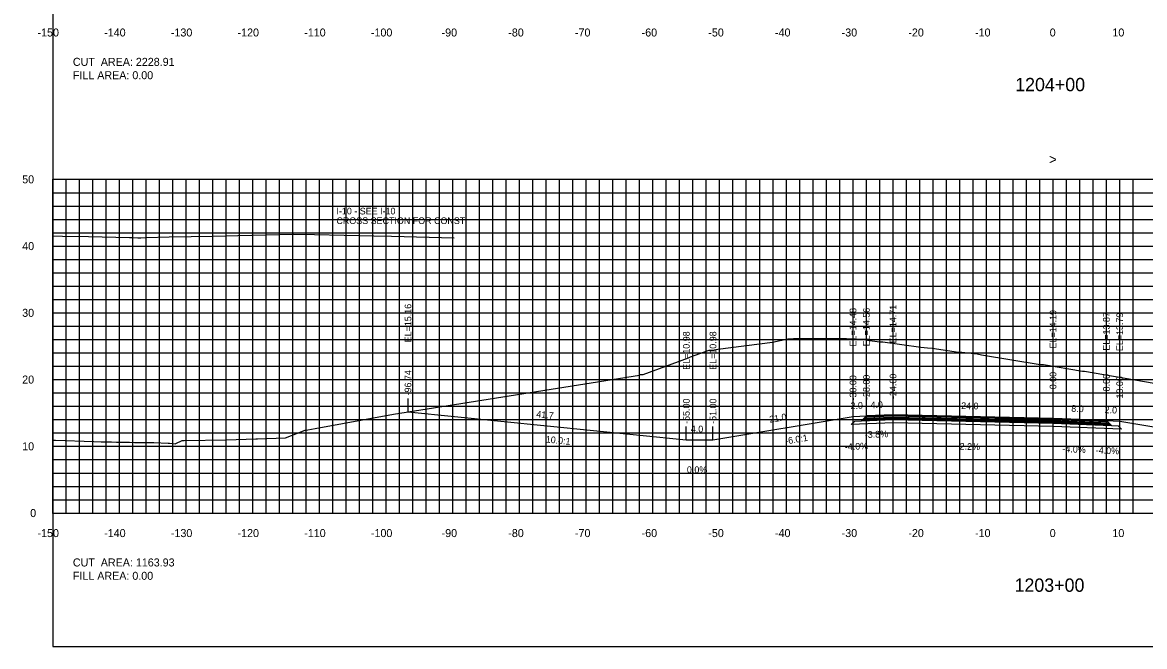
# Model space of a CAD drawing. Extents: x 1797305 to 1804485, y 245831 to 250849.
# Drawn here: x 1802476.4 to 1802644.7, y 250079.4 to 250172.9 of the extents above; entities that cross this region are included whole.
import ezdxf

# ---------------------------------------------------------------- set-up
doc = ezdxf.new("R2010")
doc.units = 0
for name, color, linetype in [('1', 7, 'Continuous'), ('10', 7, 'Continuous'), ('29', 7, 'Continuous'), ('60', 7, 'Continuous'), ('ALIGN-CARP', 7, 'Continuous'), ('BASE', 7, 'Continuous'), ('CL-CNST', 7, 'Continuous'), ('EDPV-LINE', 7, 'Continuous'), ('Level 31', 7, 'Continuous'), ('Level 62', 7, 'Continuous'), ('LIMT-CSLINE', 7, 'Continuous'), ('M-ROADS', 7, 'Continuous'), ('SURVEY - DRAINAGE - Area Shapes', 7, 'Continuous'), ('SURVEY - DRAINAGE - Bridge Hydraulic Data - Points - Locators', 7, 'Continuous')]:
    doc.layers.add(name, color=color, linetype=linetype)

msp = doc.modelspace()

# ---------------------------------------------------------------- linework, layer by layer
for p, q in [((1802534.26, 250114.59), (1802534.26, 250116.59)), ((1802601, 250113.92), (1802601, 250115.92)), ((1802603, 250114), (1802603, 250116)), ((1802607, 250114.15), (1802607, 250116.15)), ((1802631, 250113.62), (1802631, 250115.62)), ((1802639, 250113.3), (1802639, 250115.3)), ((1802641, 250113.22), (1802641, 250115.22)), ((1802576, 250110.42), (1802576, 250112.42)), ((1802580, 250110.42), (1802580, 250112.42))]:
    msp.add_line(p, q)
msp.add_lwpolyline([(1802481, 250079.43), (1802781, 250079.43), (1802781, 250269.43), (1802481, 250269.43)], close=True)
at = {"layer": '29'}
for p, q in [((1802481, 250149.43), (1802781, 250149.43)), ((1802481, 250099.43), (1802481, 250149.43)), ((1802483, 250099.43), (1802483, 250149.43)), ((1802485, 250099.43), (1802485, 250149.43)), ((1802487, 250099.43), (1802487, 250149.43)), ((1802489, 250099.43), (1802489, 250149.43)), ((1802491, 250099.43), (1802491, 250149.43)), ((1802493, 250099.43), (1802493, 250149.43)), ((1802495, 250099.43), (1802495, 250149.43)), ((1802497, 250099.43), (1802497, 250149.43)), ((1802499, 250099.43), (1802499, 250149.43)), ((1802501, 250099.43), (1802501, 250149.43)), ((1802503, 250099.43), (1802503, 250149.43)), ((1802505, 250099.43), (1802505, 250149.43)), ((1802507, 250099.43), (1802507, 250149.43)), ((1802509, 250099.43), (1802509, 250149.43)), ((1802511, 250099.43), (1802511, 250149.43)), ((1802513, 250099.43), (1802513, 250149.43)), ((1802515, 250099.43), (1802515, 250149.43)), ((1802517, 250099.43), (1802517, 250149.43)), ((1802519, 250099.43), (1802519, 250149.43)), ((1802521, 250099.43), (1802521, 250149.43)), ((1802523, 250099.43), (1802523, 250149.43)), ((1802525, 250099.43), (1802525, 250149.43)), ((1802527, 250099.43), (1802527, 250149.43)), ((1802529, 250099.43), (1802529, 250149.43)), ((1802531, 250099.43), (1802531, 250149.43)), ((1802533, 250099.43), (1802533, 250149.43)), ((1802535, 250099.43), (1802535, 250149.43)), ((1802537, 250099.43), (1802537, 250149.43)), ((1802539, 250099.43), (1802539, 250149.43)), ((1802541, 250099.43), (1802541, 250149.43)), ((1802543, 250099.43), (1802543, 250149.43)), ((1802545, 250099.43), (1802545, 250149.43)), ((1802547, 250099.43), (1802547, 250149.43)), ((1802549, 250099.43), (1802549, 250149.43)), ((1802551, 250099.43), (1802551, 250149.43)), ((1802553, 250099.43), (1802553, 250149.43)), ((1802555, 250099.43), (1802555, 250149.43)), ((1802557, 250099.43), (1802557, 250149.43)), ((1802559, 250099.43), (1802559, 250149.43)), ((1802561, 250099.43), (1802561, 250149.43)), ((1802563, 250099.43), (1802563, 250149.43)), ((1802565, 250099.43), (1802565, 250149.43)), ((1802567, 250099.43), (1802567, 250149.43)), ((1802569, 250099.43), (1802569, 250149.43)), ((1802571, 250099.43), (1802571, 250149.43)), ((1802573, 250099.43), (1802573, 250149.43)), ((1802575, 250099.43), (1802575, 250149.43)), ((1802577, 250099.43), (1802577, 250149.43)), ((1802579, 250099.43), (1802579, 250149.43)), ((1802581, 250099.43), (1802581, 250149.43)), ((1802583, 250099.43), (1802583, 250149.43)), ((1802585, 250099.43), (1802585, 250149.43)), ((1802587, 250099.43), (1802587, 250149.43)), ((1802589, 250099.43), (1802589, 250149.43)), ((1802591, 250099.43), (1802591, 250149.43)), ((1802593, 250099.43), (1802593, 250149.43)), ((1802595, 250099.43), (1802595, 250149.43)), ((1802597, 250099.43), (1802597, 250149.43)), ((1802599, 250099.43), (1802599, 250149.43)), ((1802601, 250099.43), (1802601, 250149.43)), ((1802603, 250099.43), (1802603, 250149.43)), ((1802605, 250099.43), (1802605, 250149.43)), ((1802607, 250099.43), (1802607, 250149.43)), ((1802609, 250099.43), (1802609, 250149.43)), ((1802611, 250099.43), (1802611, 250149.43)), ((1802613, 250099.43), (1802613, 250149.43)), ((1802615, 250099.43), (1802615, 250149.43)), ((1802617, 250099.43), (1802617, 250149.43)), ((1802619, 250099.43), (1802619, 250149.43)), ((1802621, 250099.43), (1802621, 250149.43)), ((1802623, 250099.43), (1802623, 250149.43)), ((1802625, 250099.43), (1802625, 250149.43)), ((1802627, 250099.43), (1802627, 250149.43)), ((1802629, 250099.43), (1802629, 250149.43)), ((1802631, 250099.43), (1802631, 250149.43)), ((1802633, 250099.43), (1802633, 250149.43)), ((1802635, 250099.43), (1802635, 250149.43)), ((1802637, 250099.43), (1802637, 250149.43)), ((1802639, 250099.43), (1802639, 250149.43)), ((1802641, 250099.43), (1802641, 250149.43)), ((1802643, 250099.43), (1802643, 250149.43)), ((1802481, 250147.43), (1802781, 250147.43)), ((1802481, 250145.43), (1802781, 250145.43)), ((1802481, 250143.43), (1802781, 250143.43)), ((1802481, 250141.43), (1802781, 250141.43)), ((1802481, 250139.43), (1802781, 250139.43)), ((1802481, 250137.43), (1802781, 250137.43)), ((1802481, 250135.43), (1802781, 250135.43)), ((1802481, 250133.43), (1802781, 250133.43)), ((1802481, 250131.43), (1802781, 250131.43)), ((1802481, 250129.43), (1802781, 250129.43)), ((1802481, 250127.43), (1802781, 250127.43)), ((1802481, 250125.43), (1802781, 250125.43)), ((1802481, 250123.43), (1802781, 250123.43)), ((1802481, 250121.43), (1802781, 250121.43)), ((1802481, 250119.43), (1802781, 250119.43)), ((1802481, 250117.43), (1802781, 250117.43)), ((1802481, 250115.43), (1802781, 250115.43)), ((1802481, 250113.43), (1802781, 250113.43)), ((1802481, 250111.43), (1802781, 250111.43)), ((1802481, 250109.43), (1802781, 250109.43)), ((1802481, 250107.43), (1802781, 250107.43)), ((1802481, 250105.43), (1802781, 250105.43)), ((1802481, 250103.43), (1802781, 250103.43)), ((1802481, 250101.43), (1802781, 250101.43)), ((1802481, 250099.43), (1802781, 250099.43))]:
    msp.add_line(p, q, dxfattribs=at)
at = {"layer": 'ALIGN-CARP'}
msp.add_lwpolyline([(1802601.25, 250113.21), (1802602.25, 250113.25), (1802607, 250113.43), (1802631, 250112.9), (1802639.75, 250112.55), (1802640.75, 250112.51), (1802641.27, 250111.99), (1802631, 250112.4), (1802607, 250112.93), (1802600.73, 250112.69)], close=True, dxfattribs=at)
at = {"layer": 'CL-CNST'}
for points in [[(1802481, 250140.95), (1802482.45, 250140.92), (1802486.33, 250140.84), (1802492.49, 250140.71), (1802492.95, 250140.7), (1802493.74, 250140.68), (1802493.75, 250140.68), (1802493.75, 250140.68), (1802494.2, 250140.69), (1802495, 250140.71), (1802498.44, 250140.79), (1802505.04, 250140.93), (1802508.72, 250141.02), (1802517.1, 250141.2), (1802520.26, 250141.14), (1802529.15, 250140.95), (1802531.81, 250140.89), (1802541.2, 250140.69)], [(1802534.26, 250114.59), (1802576, 250110.42), (1802580, 250110.42), (1802601, 250113.92), (1802603, 250114), (1802607, 250114.15), (1802631, 250113.62), (1802639, 250113.3), (1802641, 250113.22), (1802662, 250109.72), (1802666, 250109.72), (1802682.18, 250113.76)]]:
    msp.add_lwpolyline(points, dxfattribs=at)
at = {"layer": 'Level 31'}
for p, q in [((1802480.94, 250149.43), (1802481, 250149.43)), ((1802481, 250099.43), (1802481, 250149.43)), ((1802480.94, 250139.43), (1802481, 250139.43)), ((1802480.94, 250129.43), (1802481, 250129.43)), ((1802480.94, 250119.43), (1802481, 250119.43)), ((1802480.94, 250109.43), (1802481, 250109.43)), ((1802480.94, 250099.43), (1802481, 250099.43)), ((1802481, 250099.43), (1802781, 250099.43)), ((1802481, 250099.37), (1802481, 250099.43)), ((1802491, 250099.37), (1802491, 250099.43)), ((1802501, 250099.37), (1802501, 250099.43)), ((1802511, 250099.37), (1802511, 250099.43)), ((1802521, 250099.37), (1802521, 250099.43)), ((1802531, 250099.37), (1802531, 250099.43)), ((1802541, 250099.37), (1802541, 250099.43)), ((1802551, 250099.37), (1802551, 250099.43)), ((1802561, 250099.37), (1802561, 250099.43)), ((1802571, 250099.37), (1802571, 250099.43)), ((1802581, 250099.37), (1802581, 250099.43)), ((1802591, 250099.37), (1802591, 250099.43)), ((1802601, 250099.37), (1802601, 250099.43)), ((1802611, 250099.37), (1802611, 250099.43)), ((1802621, 250099.37), (1802621, 250099.43)), ((1802631, 250099.37), (1802631, 250099.43)), ((1802641, 250099.37), (1802641, 250099.43))]:
    msp.add_line(p, q, dxfattribs=at)
at = {"layer": 'Level 62'}
msp.add_lwpolyline([(1802639.36, 250112.94), (1802639.16, 250113.14), (1802631, 250113.47), (1802607, 250114), (1802602.85, 250113.84), (1802602.65, 250113.64), (1802607, 250113.81), (1802631, 250113.28)], close=True, dxfattribs=at)
at = {"layer": 'M-ROADS'}
msp.add_lwpolyline([(1802481, 250110.35), (1802481.07, 250110.34), (1802481.41, 250110.33), (1802487.14, 250110.15), (1802488.23, 250110.11), (1802489.81, 250110.08), (1802490.56, 250110.06), (1802492.47, 250110.03), (1802493.25, 250110.02), (1802496.15, 250110), (1802498.31, 250109.9), (1802498.5, 250109.88), (1802499.4, 250109.82), (1802499.42, 250109.83), (1802500.4, 250110.31), (1802500.71, 250110.31), (1802507.06, 250110.38), (1802511.42, 250110.56), (1802511.67, 250110.57), (1802515.91, 250110.72), (1802518.83, 250111.86), (1802519.23, 250111.91), (1802520.33, 250112.09), (1802532.08, 250114.24), (1802568.96, 250120.1), (1802569.05, 250120.2), (1802569.35, 250120.2), (1802569.54, 250120.19), (1802576.34, 250122.69), (1802576.63, 250122.84), (1802579.42, 250123.83), (1802579.48, 250123.83), (1802579.91, 250123.82), (1802580.72, 250123.99), (1802588.93, 250125.02), (1802591.23, 250125.52), (1802591.63, 250125.51), (1802591.73, 250125.51), (1802592.09, 250125.56), (1802600.01, 250125.56), (1802602.67, 250125.47), (1802603.03, 250125.36), (1802603.15, 250125.35), (1802604.95, 250125.07), (1802605.36, 250125.06), (1802605.45, 250125.06), (1802611.19, 250124.27), (1802612.17, 250124.19), (1802612.86, 250124.13), (1802616.83, 250123.56), (1802616.88, 250123.56), (1802617.33, 250123.56), (1802619.62, 250123.29), (1802620.25, 250123.14), (1802629.06, 250121.67), (1802629.38, 250121.67), (1802629.55, 250121.67), (1802635.4, 250120.71), (1802635.7, 250120.7), (1802646.17, 250118.87)], dxfattribs=at)
at = {"layer": 'SURVEY - DRAINAGE - Area Shapes'}
msp.add_lwpolyline([(1802639.16, 250113.14), (1802639, 250113.3), (1802631, 250113.62), (1802607, 250114.15), (1802603, 250114), (1802602.85, 250113.84), (1802607, 250114), (1802631, 250113.47)], close=True, dxfattribs=at)
at = {"layer": 'SURVEY - DRAINAGE - Bridge Hydraulic Data - Points - Locators'}
for points in [[(1802607, 250113.62), (1802631, 250113.09), (1802639.55, 250112.75), (1802639.75, 250112.55), (1802631, 250112.9), (1802607, 250113.43), (1802602.25, 250113.25), (1802602.45, 250113.44)], [(1802607, 250113.81), (1802631, 250113.28), (1802639.36, 250112.94), (1802639.55, 250112.75), (1802631, 250113.09), (1802607, 250113.62), (1802602.45, 250113.44), (1802602.65, 250113.64)]]:
    msp.add_lwpolyline(points, close=True, dxfattribs=at)

# ---------------------------------------------------------------- texts
for s, rotation, p in [('10.0:1', 354.2894, (1802554.88, 250110.01)), ('-6.0:1', 9.4623, (1802590.91, 250109.7))]:
    msp.add_text(s, height=1, rotation=rotation).set_placement(p)
at = {"layer": '1'}
for s, p in [('1204+00', (1802625.32, 250162.63)), ('1203+00', (1802625.22, 250087.63))]:
    msp.add_text(s, height=2, dxfattribs=at).set_placement(p)
at = {"layer": '10'}
for s, p in [('-150', (1802478.7, 250170.83)), ('-140', (1802488.7, 250170.83)), ('-130', (1802498.7, 250170.83)), ('-120', (1802508.7, 250170.83)), ('-110', (1802518.7, 250170.83)), ('-100', (1802528.7, 250170.83)), ('-90', (1802539.3, 250170.83)), ('-80', (1802549.3, 250170.83)), ('-70', (1802559.3, 250170.83)), ('-60', (1802569.3, 250170.83)), ('-50', (1802579.3, 250170.83)), ('-40', (1802589.3, 250170.83)), ('-30', (1802599.3, 250170.83)), ('-20', (1802609.3, 250170.83)), ('-10', (1802619.3, 250170.83)), ('0', (1802630.5, 250170.83)), ('10', (1802639.9, 250170.83)), ('-150', (1802478.7, 250095.83)), ('-140', (1802488.7, 250095.83)), ('-130', (1802498.7, 250095.83)), ('-120', (1802508.7, 250095.83)), ('-110', (1802518.7, 250095.83)), ('-100', (1802528.7, 250095.83)), ('-90', (1802539.3, 250095.83)), ('-80', (1802549.3, 250095.83)), ('-70', (1802559.3, 250095.83)), ('-60', (1802569.3, 250095.83)), ('-50', (1802579.3, 250095.83)), ('-40', (1802589.3, 250095.83)), ('-30', (1802599.3, 250095.83)), ('-20', (1802609.3, 250095.83)), ('-10', (1802619.3, 250095.83)), ('0', (1802630.5, 250095.83)), ('10', (1802639.9, 250095.83))]:
    msp.add_text(s, height=1.2, dxfattribs=at).set_placement(p)
at = {"layer": '60'}
for s, p in [('50', (1802476.4, 250148.83)), ('40', (1802476.4, 250138.83)), ('30', (1802476.4, 250128.83)), ('20', (1802476.4, 250118.83)), ('10', (1802476.4, 250108.83)), ('0', (1802477.6, 250098.83))]:
    msp.add_text(s, height=1.2, dxfattribs=at).set_placement(p)
at = {"layer": 'BASE'}
for s, rotation, p in [('2.0', 2.2906, (1802600.64, 250115)), ('4.0', 2.1586, (1802603.64, 250115.12)), ('24.0', 358.7397, (1802617.21, 250115.02)), ('8.0', 357.7094, (1802633.72, 250114.61)), ('2.0', 357.7094, (1802638.72, 250114.41)), ('41.7', 354.2894, (1802553.47, 250113.77)), ('21.0', 9.4623, (1802588.53, 250112.95)), ('-3.8%', 2.1586, (1802602.78, 250110.67)), ('-4.0%', 2.2906, (1802599.79, 250108.86)), ('2.2%', 358.7397, (1802616.98, 250108.93)), ('-4.0%', 357.7094, (1802632.39, 250108.56)), ('-4.0%', 357.7094, (1802637.39, 250108.36))]:
    msp.add_text(s, height=1, rotation=rotation, dxfattribs=at).set_placement(p)
for s, p in [('4.0', (1802576.68, 250111.52)), ('0.0%', (1802576.09, 250105.42))]:
    msp.add_text(s, height=1, dxfattribs=at).set_placement(p)
at = {"layer": 'EDPV-LINE'}
for s, p in [('CUT  AREA: 2228.91', (1802484, 250166.43)), ('FILL AREA: 0.00', (1802484, 250164.43)), ('CUT  AREA: 1163.93', (1802484, 250091.43)), ('FILL AREA: 0.00', (1802484, 250089.43))]:
    msp.add_text(s, height=1.2, dxfattribs=at).set_placement(p)
at = {"layer": 'Level 31'}
for s, height, p in [('>', 1.5, (1802630.39, 250151.68)), ('-', 0.0001, (1802481, 250099.43))]:
    msp.add_text(s, height=height, dxfattribs=at).set_placement(p)
at = {"layer": 'LIMT-CSLINE'}
for s, p in [('I-10 - SEE I-10', (1802523.53, 250144.17)), ('CROSS SECTION FOR CONST ', (1802523.53, 250142.73))]:
    msp.add_text(s, height=1, dxfattribs=at).set_placement(p)
for s, p in [('EL=15.16', (1802534.76, 250125.01)), ('EL=14.48', (1802601.5, 250124.39)), ('EL=14.56', (1802603.5, 250124.42)), ('EL=14.71', (1802607.5, 250124.87)), ('EL=14.19', (1802631.5, 250124.09)), ('EL=13.87', (1802639.5, 250123.77)), ('EL=13.79', (1802641.5, 250123.69)), ('EL=10.98', (1802576.5, 250120.89)), ('EL=10.98', (1802580.5, 250120.89)), ('-96.74', (1802534.76, 250117.05)), ('-30.00', (1802601.5, 250116.29)), ('-28.00', (1802603.5, 250116.37)), ('-24.00', (1802607.5, 250116.52)), ('0.00', (1802631.5, 250117.98)), ('8.00', (1802639.5, 250117.66)), ('10.00', (1802641.5, 250116.59)), ('-55.00', (1802576.5, 250112.79)), ('-51.00', (1802580.5, 250112.79))]:
    msp.add_text(s, height=1, rotation=90, dxfattribs=at).set_placement(p)

doc.saveas('drawing.dxf')
